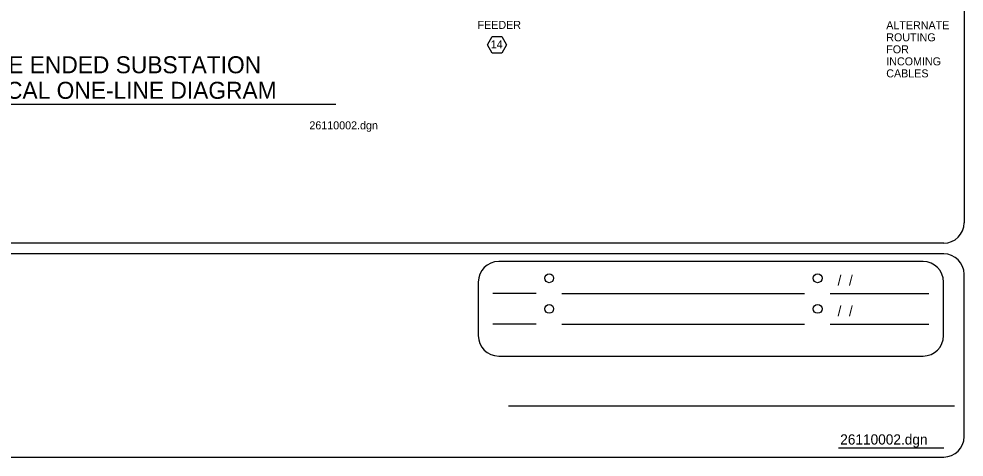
# Model space of a CAD drawing. Extents: x 10251 to 10396, y 10092 to 10197.
# Drawn here: x 10316 to 10394.7, y 10092.4 to 10128.8 of the extents above; entities that cross this region are included whole.
import ezdxf

# ---------------------------------------------------------------- set-up
doc = ezdxf.new("R2010")
doc.units = 0
for name, color, linetype in [('G-ANNO-PROJ', 7, 'Continuous'), ('G-ANNO-TEXT', 7, 'Continuous'), ('G-ANNO-TTLB', 7, 'Continuous')]:
    doc.layers.add(name, color=color, linetype=linetype)

msp = doc.modelspace()

# ---------------------------------------------------------------- linework, layer by layer
at = {"layer": 'G-ANNO-TEXT'}
msp.add_line((10303.885, 10121.741), (10342.41, 10121.741), dxfattribs=at)
msp.add_lwpolyline([(10356.605, 10126.664), (10356.213, 10125.985), (10355.429, 10125.985), (10355.037, 10126.664), (10355.429, 10127.344), (10356.213, 10127.344)], close=True, dxfattribs=at)
at = {"layer": 'G-ANNO-TTLB'}
for p, q in [((10394.706, 10195.228), (10394.706, 10111.866)), ((10393.006, 10110.166), (10254.096, 10110.166)), ((10354.26, 10106.94), (10354.26, 10102.482)), ((10393, 10102.482), (10393, 10106.94)), ((10359.08, 10105.974), (10355.461, 10105.974)), ((10361.202, 10105.974), (10381.422, 10105.974)), ((10383.544, 10105.974), (10391.777, 10105.974)), ((10359.08, 10103.424), (10355.461, 10103.424)), ((10361.202, 10103.424), (10381.422, 10103.424)), ((10383.544, 10103.424), (10391.777, 10103.424)), ((10356.774, 10096.629), (10393.903, 10096.629)), ((10384.261, 10093.15), (10393.006, 10093.15))]:
    msp.add_line(p, q, dxfattribs=at)
for points in [[(10393.006, 10109.279), (10254.096, 10109.279)], [(10391.3, 10108.64), (10355.96, 10108.64)], [(10394.706, 10094.08), (10394.706, 10107.579)], [(10355.96, 10100.782), (10391.3, 10100.782)], [(10254.096, 10092.38), (10393.006, 10092.38)]]:
    msp.add_lwpolyline(points, dxfattribs=at)
for centre in [(10360.171, 10107.249), (10382.513, 10107.249), (10360.171, 10104.699), (10382.513, 10104.699)]:
    msp.add_circle(centre, 0.364, dxfattribs=at)
for centre, start, end in [((10393.006, 10111.866), 270, 360), ((10393.006, 10107.579), 0, 90), ((10355.96, 10106.94), 90, 180), ((10391.3, 10106.94), 0, 90), ((10355.96, 10102.482), 180, 270), ((10391.3, 10102.482), 270, 0), ((10393.006, 10094.08), 270, 0)]:
    msp.add_arc(centre, 1.7, start, end, dxfattribs=at)

# ---------------------------------------------------------------- texts
at = {"layer": 'G-ANNO-PROJ'}
for s, p in [('  /  /  ', (10383.544, 10106.661)), ('  /  /  ', (10383.544, 10104.111)), ('26110002.dgn ', (10384.393, 10093.422))]:
    msp.add_text(s, height=0.85, dxfattribs=at).set_placement(p)
at = {"layer": 'G-ANNO-TEXT'}
for s, height, p in [('FEEDER', 0.6667, (10354.201, 10127.991)), ('ALTERNATE', 0.6667, (10388.226, 10127.957)), ('14', 0.6667, (10355.298, 10126.374)), ('ROUTING', 0.6667, (10388.226, 10126.957)), ('FOR', 0.6667, (10388.226, 10125.957)), ('DOUBLE ENDED SUBSTATION', 1.41667, (10308.599, 10124.299)), ('INCOMING', 0.6667, (10388.226, 10124.957)), ('CABLES', 0.6667, (10388.226, 10123.957)), ('ELECTRICAL ONE-LINE DIAGRAM', 1.41667, (10306.943, 10122.174)), ('26110002.dgn', 0.66667, (10340.199, 10119.635))]:
    msp.add_text(s, height=height, dxfattribs=at).set_placement(p)

doc.saveas('drawing.dxf')
